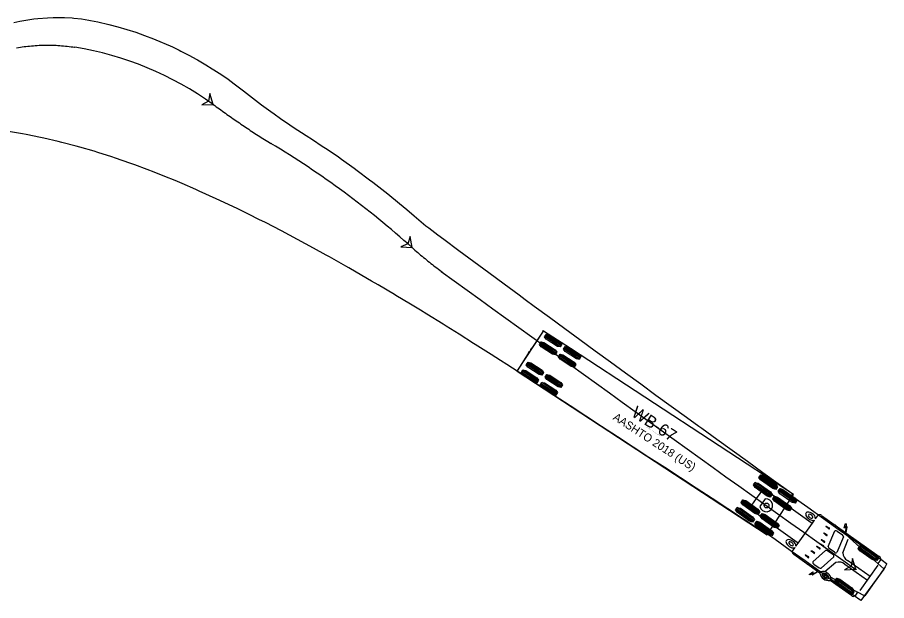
# Model space of a CAD drawing. Extents: x 973688 to 979179, y 703586 to 707602.
# Drawn here: x 977227.3 to 977381.2, y 703955.6 to 704058.8 of the extents above; entities that cross this region are included whole.
import ezdxf

# ---------------------------------------------------------------- set-up
doc = ezdxf.new("R2010")
doc.units = 0
doc.layers.add('SB Right', color=7, linetype='Continuous')

msp = doc.modelspace()

# ---------------------------------------------------------------- linework, layer by layer
at = {"layer": 'SB Right'}
for p, q in [((977315.78, 703996.2), (977320.43, 704003.32)), ((977320.34, 704003.32), (977318.35, 704000.28)), ((977320.34, 704003.32), (977320.34, 704003.32)), ((977320.37, 704003.36), (977320.35, 704003.34)), ((977320.43, 704003.32), (977320.37, 704003.36)), ((977325.17, 704000.22), (977320.43, 704003.32)), ((977323.41, 704000.55), (977320.64, 704002.36)), ((977323.53, 704000.74), (977320.77, 704002.55)), ((977323.66, 704000.94), (977320.89, 704002.74)), ((977318.18, 704000.02), (977317.9, 703999.58)), ((977318.27, 704000.28), (977318.13, 704000.06)), ((977318.19, 704000.02), (977318.33, 704000.25)), ((977318.33, 704000.25), (977318.27, 704000.28)), ((977318.27, 704000.28), (977318.27, 704000.28)), ((977318.35, 704000.28), (977318.33, 704000.25)), ((977322.5, 703999.17), (977319.74, 704000.98)), ((977322.63, 703999.36), (977319.87, 704001.17)), ((977322.75, 703999.56), (977319.99, 704001.36)), ((977326.76, 703998.37), (977323.99, 704000.17)), ((977326.88, 703998.56), (977324.12, 704000.36)), ((977327.01, 703998.75), (977324.24, 704000.55)), ((977364.68, 703974.42), (977325.17, 704000.22)), ((977317.73, 703999.33), (977315.74, 703996.28)), ((977317.84, 703999.62), (977317.69, 703999.4)), ((977317.69, 703999.4), (977317.69, 703999.39)), ((977317.69, 703999.39), (977317.75, 703999.36)), ((977317.75, 703999.36), (977317.73, 703999.33)), ((977317.75, 703999.36), (977317.9, 703999.58)), ((977318.04, 703999.8), (977318.1, 703999.76)), ((977325.85, 703996.98), (977323.09, 703998.79)), ((977325.98, 703997.18), (977323.22, 703998.98)), ((977326.1, 703997.37), (977323.34, 703999.17)), ((977320.16, 703995.59), (977317.4, 703997.39)), ((977320.29, 703995.78), (977317.52, 703997.58)), ((977320.41, 703995.97), (977317.65, 703997.77)), ((977315.73, 703996.26), (977315.72, 703996.24)), ((977315.72, 703996.24), (977315.78, 703996.2)), ((977315.74, 703996.28), (977315.74, 703996.28)), ((977315.78, 703996.2), (977320.52, 703993.11)), ((977319.26, 703994.2), (977316.5, 703996.01)), ((977319.39, 703994.4), (977316.62, 703996.2)), ((977319.51, 703994.59), (977316.75, 703996.39)), ((977323.76, 703993.78), (977321, 703995.59)), ((977322.73, 703992.21), (977319.97, 703994.01)), ((977322.86, 703992.4), (977320.1, 703994.2)), ((977323.51, 703993.4), (977320.75, 703995.2)), ((977323.64, 703993.59), (977320.87, 703995.39)), ((977322.61, 703992.02), (977319.85, 703993.82)), ((977320.52, 703993.11), (977360.03, 703967.3)), ((977361.55, 703975.35), (977358.57, 703977.48)), ((977361.69, 703975.54), (977358.7, 703977.67)), ((977361.82, 703975.72), (977358.84, 703977.85)), ((977360.6, 703974.01), (977357.61, 703976.14)), ((977360.73, 703974.19), (977357.74, 703976.32)), ((977360.86, 703974.38), (977357.88, 703976.51)), ((977358.14, 703973.72), (977359.4, 703975.48)), ((977359.4, 703975.48), (977367.83, 703969.46)), ((977365.24, 703973.28), (977362.25, 703975.41)), ((977364.15, 703971.75), (977361.16, 703973.88)), ((977364.28, 703971.94), (977361.3, 703974.07)), ((977364.97, 703972.91), (977361.99, 703975.04)), ((977365.11, 703973.1), (977362.12, 703975.23)), ((977362.36, 703970.86), (977364.68, 703974.42)), ((977358.4, 703970.93), (977355.41, 703973.06)), ((977358.53, 703971.11), (977355.55, 703973.24)), ((977358.66, 703971.3), (977355.68, 703973.43)), ((977356.88, 703971.96), (977358.14, 703973.72)), ((977359.66, 703973.62), (977358.72, 703972.31)), ((977364.01, 703971.57), (977361.03, 703973.7)), ((977357.44, 703969.58), (977354.45, 703971.72)), ((977357.57, 703969.77), (977354.59, 703971.9)), ((977357.7, 703969.96), (977354.72, 703972.09)), ((977365.31, 703965.94), (977356.88, 703971.96)), ((977361.95, 703968.67), (977358.96, 703970.8)), ((977362.08, 703968.86), (977359.1, 703970.99)), ((977360.03, 703967.3), (977362.36, 703970.86)), ((977368.58, 703970.11), (977369.08, 703970.8)), ((977360.86, 703967.14), (977357.87, 703969.27)), ((977360.99, 703967.33), (977358.01, 703969.46)), ((977361.12, 703967.52), (977358.14, 703969.65)), ((977361.82, 703968.49), (977358.83, 703970.62)), ((977365.51, 703965.8), (977368.02, 703969.32)), ((977367.83, 703969.46), (977368.02, 703969.32)), ((977368.02, 703969.32), (977368.42, 703969.88)), ((977369.65, 703970.72), (977373.86, 703967.71)), ((977373.67, 703968.54), (977373.87, 703969.28)), ((977373.87, 703969.28), (977373.88, 703969.28)), ((977373.88, 703969.28), (977373.97, 703969.21)), ((977370.41, 703968.76), (977370.47, 703968.83)), ((977370.84, 703968.41), (977370.41, 703968.76)), ((977370.47, 703968.83), (977370.94, 703968.54)), ((977370.81, 703965.19), (977371.99, 703967.96)), ((977372.03, 703969.02), (977379.61, 703962.19)), ((977372.4, 703967.91), (977373.33, 703967.25)), ((977373.75, 703968.48), (977373.67, 703968.54)), ((977373.96, 703968.76), (977373.75, 703968.48)), ((977373.86, 703967.71), (977374.05, 703968.68)), ((977373.86, 703967.71), (977373.95, 703967.66)), ((977374.14, 703968.64), (977373.95, 703967.67)), ((977373.97, 703968.76), (977373.96, 703968.76)), ((977373.97, 703969.21), (977373.97, 703969.21)), ((977373.97, 703969.21), (977373.98, 703968.81)), ((977373.97, 703968.76), (977373.98, 703968.78)), ((977374.03, 703968.71), (977373.97, 703968.76)), ((977373.98, 703968.78), (977373.98, 703968.81)), ((977373.98, 703968.81), (977373.98, 703968.81)), ((977373.98, 703968.81), (977374.05, 703968.76)), ((977374.05, 703968.68), (977374.03, 703968.71)), ((977374.03, 703968.71), (977374.03, 703968.71)), ((977374.03, 703968.71), (977374.03, 703968.71)), ((977374.05, 703968.68), (977374.05, 703968.68)), ((977369.58, 703966.36), (977369.64, 703966.43)), ((977370.01, 703966.01), (977369.58, 703966.36)), ((977369.64, 703966.43), (977370.11, 703966.14)), ((977370.02, 703967.54), (977370.07, 703967.62)), ((977370.47, 703967.18), (977370.02, 703967.54)), ((977370.07, 703967.62), (977370.56, 703967.32)), ((977373.53, 703966.9), (977372.35, 703964.13)), ((977373.43, 703964.11), (977374.35, 703966.49)), ((977373.95, 703967.67), (977373.95, 703967.65)), ((977373.95, 703967.65), (977379.86, 703963.43)), ((977364.45, 703964.32), (977364.94, 703965.01)), ((977365.11, 703965.24), (977365.51, 703965.8)), ((977365.51, 703965.8), (977365.31, 703965.94)), ((977368.76, 703965.21), (977368.82, 703965.28)), ((977369.19, 703964.86), (977368.76, 703965.21)), ((977368.82, 703965.28), (977369.29, 703964.99)), ((977369.43, 703965.6), (977369.48, 703965.68)), ((977369.85, 703965.25), (977369.43, 703965.6)), ((977369.48, 703965.68), (977369.95, 703965.39)), ((977371.93, 703964.19), (977371.01, 703964.85)), ((977379.14, 703962.8), (977376.15, 703964.93)), ((977379.27, 703962.99), (977376.28, 703965.11)), ((977379.4, 703963.18), (977376.41, 703965.3)), ((977368.92, 703960.8), (977364.71, 703963.8)), ((977366.76, 703963.65), (977366.82, 703963.72)), ((977367.19, 703963.29), (977366.76, 703963.65)), ((977366.82, 703963.72), (977367.29, 703963.43)), ((977367.78, 703964.41), (977367.84, 703964.49)), ((977368.21, 703964.06), (977367.78, 703964.41)), ((977367.84, 703964.49), (977368.31, 703964.2)), ((977370.31, 703964.5), (977368.08, 703962.49)), ((977369.59, 703961.38), (977371.82, 703963.39)), ((977371.63, 703963.77), (977370.71, 703964.42)), ((977379.12, 703962.95), (977379.36, 703963.28)), ((977379.36, 703963.28), (977379.65, 703963.08)), ((977367.09, 703962.1), (977369.55, 703960.74)), ((977368.27, 703962.11), (977369.19, 703961.46)), ((977372.19, 703962.37), (977370.23, 703960.72)), ((977377.75, 703959.2), (977373.77, 703962.04)), ((977378.24, 703959.88), (977374.26, 703962.72)), ((977376.46, 703957.4), (977379.69, 703961.92)), ((977379.41, 703962.74), (977379.12, 703962.95)), ((977379.65, 703963.08), (977379.41, 703962.74)), ((977380.11, 703962.89), (977379.61, 703962.19)), ((977379.61, 703962.19), (977379.61, 703962.19)), ((977379.61, 703962.19), (977380.67, 703961.23)), ((977367.45, 703960.28), (977368.08, 703960.71)), ((977367.54, 703960.21), (977367.45, 703960.28)), ((977367.45, 703960.28), (977367.45, 703960.28)), ((977367.55, 703960.21), (977367.54, 703960.21)), ((977367.93, 703960.33), (977367.55, 703960.21)), ((977367.95, 703960.34), (977367.93, 703960.33)), ((977368, 703960.28), (977367.93, 703960.33)), ((977367.93, 703960.33), (977367.93, 703960.33)), ((977367.97, 703960.36), (977367.95, 703960.34)), ((977368.16, 703960.65), (977367.97, 703960.36)), ((977367.97, 703960.36), (977367.97, 703960.36)), ((977367.97, 703960.36), (977368.04, 703960.31)), ((977368.04, 703960.31), (977368.04, 703960.31)), ((977368.04, 703960.31), (977368.04, 703960.31)), ((977368.04, 703960.31), (977368.07, 703960.3)), ((977368.07, 703960.3), (977368.92, 703960.8)), ((977368.07, 703960.3), (977368.07, 703960.3)), ((977368.08, 703960.71), (977368.16, 703960.65)), ((977369, 703960.73), (977368.13, 703960.24)), ((977368.92, 703960.8), (977369.01, 703960.74)), ((977369.01, 703960.73), (977369, 703960.73)), ((977369.36, 703960.49), (977369.01, 703960.73)), ((977380.64, 703961.17), (977378.97, 703958.84)), ((977380.67, 703961.23), (977380.64, 703961.17)), ((977374.92, 703956.52), (977371.14, 703959.21)), ((977371.27, 703959.79), (977376.02, 703957.16)), ((977375.02, 703957.04), (977372.03, 703959.16)), ((977375.15, 703957.22), (977372.17, 703959.35)), ((977375.29, 703957.41), (977372.3, 703959.53)), ((977378.97, 703958.84), (977377.31, 703956.51)), ((977375.14, 703957.37), (977374.9, 703957.03)), ((977374.9, 703957.03), (977375.19, 703956.83)), ((977375.43, 703957.16), (977375.14, 703957.37)), ((977375.19, 703956.83), (977375.43, 703957.16)), ((977376.01, 703957.15), (977375.51, 703956.45)), ((977376.02, 703957.16), (977376.01, 703957.15)), ((977377.27, 703956.46), (977376.02, 703957.16)), ((977377.31, 703956.51), (977377.27, 703956.46))]:
    msp.add_line(p, q, dxfattribs=at)
for points in [[(977226.66, 704057.93), (977227.72, 704058.15), (977229.48, 704058.45), (977230.18, 704058.55), (977230.87, 704058.63), (977232.59, 704058.76), (977233.61, 704058.8), (977234.28, 704058.81), (977235.63, 704058.79), (977236.96, 704058.71), (977237.29, 704058.68), (977238.61, 704058.54), (977239.91, 704058.34), (977240.23, 704058.28), (977241.52, 704058.01), (977243.44, 704057.57), (977245.04, 704057.14), (977246.64, 704056.68), (977248.22, 704056.17), (977249.79, 704055.62), (977251.35, 704055.03), (977252.89, 704054.4), (977253.2, 704054.26), (977254.73, 704053.58), (977255.93, 704053), (977256.23, 704052.86), (977257.72, 704052.09), (977258.9, 704051.45), (977259.19, 704051.29), (977260.64, 704050.44), (977261.78, 704049.74), (977262.07, 704049.56), (977263.47, 704048.63), (977264.58, 704047.86), (977265.68, 704047.07), (977267.3, 704045.84), (977269.98, 704043.77), (977270.52, 704043.36), (977272.16, 704042.14), (977272.72, 704041.74), (977273.83, 704040.94), (977275.52, 704039.78), (977276.09, 704039.41), (977278.39, 704037.94), (977279.54, 704037.19), (977281.26, 704036.06), (977282.12, 704035.49), (977284.1, 704034.13), (977284.66, 704033.74), (977286.89, 704032.14), (977287.45, 704031.74), (977289.64, 704030.1), (977290.18, 704029.69), (977292.32, 704028.02), (977292.85, 704027.6), (977294.95, 704025.9), (977296.25, 704024.82), (977297.53, 704023.73), (977299.56, 704021.96), (977300.09, 704021.56), (977301.7, 704020.36), (977302.77, 704019.57), (977305.43, 704017.6), (977308.09, 704015.63), (977310.75, 704013.66), (977313.43, 704011.69), (977316.11, 704009.71), (977317.18, 704008.92), (977318.79, 704007.73), (977321.48, 704005.76), (977324.17, 704003.79), (977326.86, 704001.82), (977329.55, 703999.85), (977332.25, 703997.88), (977334.94, 703995.92), (977337.63, 703993.96), (977340.33, 703992), (977343.03, 703990.04), (977345.73, 703988.08), (977347.89, 703986.52), (977348.43, 703986.13), (977351.13, 703984.18), (977353.83, 703982.23), (977356.53, 703980.28), (977359.24, 703978.33), (977361.94, 703976.38), (977364.39, 703974.63), (977364.45, 703974.12), (977367.2, 703972.16), (977369.98, 703970.18), (977372.78, 703968.18), (977375.57, 703966.19), (977377.58, 703964.75), (977378.52, 703964.08), (977379.45, 703963.42), (977380.35, 703962.78), (977381.12, 703962.22), (977381.16, 703962.11), (977380.88, 703961.64), (977380.02, 703960.33), (977376.58, 703955.64), (977376.33, 703955.81), (977376.25, 703955.87), (977375.58, 703956.35), (977374.67, 703956.99), (977373.77, 703957.63), (977372.89, 703958.26), (977372.01, 703958.88), (977369.35, 703960.78), (977366.71, 703962.65), (977364.07, 703964.53), (977361.41, 703966.43), (977360.07, 703967.38), (977359.74, 703967.49), (977358.63, 703968.21), (977355.85, 703970.03), (977353.05, 703971.86), (977350.26, 703973.68), (977347.47, 703975.51), (977344.67, 703977.33), (977341.88, 703979.16), (977339.08, 703980.98), (977336.29, 703982.81), (977333.5, 703984.63), (977330.71, 703986.45), (977327.91, 703988.28), (977325.12, 703990.1), (977322.33, 703991.93), (977319.54, 703993.75), (977318.7, 703994.3), (977316.74, 703995.57), (977313.94, 703997.38), (977312.82, 703998.1), (977311.14, 703999.18), (977308.32, 704000.97), (977308.04, 704001.15), (977305.49, 704002.75), (977303.21, 704004.18), (977302.64, 704004.53), (977299.77, 704006.3), (977298.62, 704007.01), (977296.89, 704008.06), (977294.3, 704009.62), (977294.01, 704009.79), (977291.13, 704011.5), (977289.99, 704012.17), (977288.27, 704013.17), (977285.97, 704014.49), (977285.4, 704014.82), (977282.54, 704016.43), (977281.97, 704016.75), (977279.69, 704018), (977278.28, 704018.78), (977276.86, 704019.54), (977274.03, 704021.04), (977271.18, 704022.5), (977270.04, 704023.08), (977268.31, 704023.94), (977266.28, 704024.93), (977265.41, 704025.35), (977262.48, 704026.73), (977259.47, 704028.09), (977258.86, 704028.36), (977256.43, 704029.41), (977255.21, 704029.93), (977253.36, 704030.68), (977251.51, 704031.41), (977250.27, 704031.89), (977248.09, 704032.7), (977247.16, 704033.04), (977244.65, 704033.91), (977244.02, 704034.12), (977241.49, 704034.92), (977240.86, 704035.12), (977238.32, 704035.86), (977237.68, 704036.03), (977235.14, 704036.7), (977234.51, 704036.86), (977231.97, 704037.44), (977231.34, 704037.58), (977228.82, 704038.09), (977228.19, 704038.21), (977225.71, 704038.64)], [(977227.14, 704053.44), (977227.47, 704053.5), (977227.8, 704053.55), (977228.13, 704053.59), (977228.46, 704053.64), (977228.79, 704053.68), (977229.12, 704053.71), (977229.45, 704053.75), (977229.79, 704053.78), (977230.12, 704053.81), (977230.45, 704053.83), (977230.78, 704053.85), (977231.12, 704053.87), (977231.45, 704053.88), (977231.78, 704053.9), (977232.12, 704053.9), (977232.45, 704053.91), (977232.78, 704053.91), (977233.12, 704053.91), (977233.45, 704053.9), (977233.78, 704053.89), (977234.12, 704053.88), (977234.45, 704053.86), (977234.78, 704053.84), (977235.11, 704053.81), (977235.45, 704053.78), (977235.78, 704053.75), (977236.11, 704053.72), (977236.44, 704053.68), (977236.77, 704053.63), (977237.1, 704053.58), (977237.43, 704053.53)], [(977261.94, 704043.4), (977261.36, 704045.32), (977261.13, 704043.98), (977259.94, 704043.33), (977261.94, 704043.4)], [(977261.94, 704043.4), (977262.21, 704043.21), (977262.48, 704043.01), (977262.75, 704042.82), (977263.03, 704042.62), (977263.3, 704042.43), (977263.57, 704042.24), (977263.84, 704042.04), (977264.11, 704041.85), (977264.38, 704041.66), (977264.65, 704041.46), (977264.93, 704041.27), (977265.2, 704041.08), (977265.47, 704040.89), (977265.75, 704040.7), (977266.02, 704040.51), (977266.29, 704040.32), (977266.57, 704040.13), (977266.84, 704039.94), (977267.12, 704039.75), (977267.4, 704039.57), (977267.67, 704039.38), (977267.95, 704039.19), (977268.23, 704039.01), (977268.5, 704038.82), (977268.78, 704038.64), (977269.06, 704038.46), (977269.34, 704038.28), (977269.62, 704038.1), (977269.9, 704037.92), (977270.18, 704037.74), (977270.46, 704037.56), (977270.75, 704037.38), (977271.03, 704037.21), (977271.31, 704037.03), (977271.6, 704036.86), (977271.88, 704036.69), (977272.17, 704036.51)], [(977297.16, 704018.09), (977296.79, 704020.05), (977296.42, 704018.75), (977295.17, 704018.24), (977297.16, 704018.09)], [(977297.16, 704018.09), (977297.41, 704017.87), (977297.66, 704017.64), (977297.91, 704017.42), (977298.16, 704017.21), (977298.42, 704016.99), (977298.67, 704016.77), (977298.92, 704016.56), (977299.18, 704016.34), (977299.44, 704016.13), (977299.69, 704015.92), (977299.95, 704015.71), (977300.21, 704015.5), (977300.47, 704015.29), (977300.74, 704015.08), (977301, 704014.88), (977301.26, 704014.68), (977301.53, 704014.48), (977301.8, 704014.28), (977302.06, 704014.08), (977302.33, 704013.88)], [(977375.72, 703961.17), (977375.13, 703963.08), (977374.9, 703961.75), (977373.72, 703961.09), (977375.72, 703961.17)]]:
    msp.add_lwpolyline(points, dxfattribs=at)
for points in [[(977261.94, 704043.4), (977261.36, 704045.32), (977261.13, 704043.98), (977259.94, 704043.33)], [(977297.16, 704018.09), (977296.79, 704020.05), (977296.42, 704018.75), (977295.17, 704018.24)], [(977323.69, 704000.98), (977323.38, 704000.51), (977322.89, 704000.61), (977320.9, 704001.91), (977320.61, 704002.31), (977320.93, 704002.79), (977321.41, 704002.68), (977323.4, 704001.38)], [(977322.79, 703999.6), (977322.47, 703999.12), (977321.99, 703999.23), (977320, 704000.53), (977319.71, 704000.93), (977320.02, 704001.41), (977320.5, 704001.3), (977322.49, 704000)], [(977327.04, 703998.8), (977326.72, 703998.32), (977326.24, 703998.43), (977324.25, 703999.73), (977323.96, 704000.12), (977324.27, 704000.6), (977324.76, 704000.49), (977326.74, 703999.19)], [(977326.13, 703997.42), (977325.82, 703996.94), (977325.34, 703997.05), (977323.35, 703998.34), (977323.06, 703998.74), (977323.37, 703999.22), (977323.85, 703999.11), (977325.84, 703997.81)], [(977320.44, 703996.02), (977320.13, 703995.54), (977319.65, 703995.65), (977317.66, 703996.95), (977317.37, 703997.34), (977317.68, 703997.82), (977318.16, 703997.71), (977320.15, 703996.41)], [(977319.54, 703994.64), (977319.23, 703994.16), (977318.75, 703994.26), (977316.76, 703995.56), (977316.47, 703995.96), (977316.78, 703996.44), (977317.26, 703996.33), (977319.25, 703995.03)], [(977323.79, 703993.83), (977323.48, 703993.35), (977323, 703993.46), (977321.01, 703994.76), (977320.72, 703995.16), (977321.03, 703995.63), (977321.51, 703995.53), (977323.5, 703994.23)], [(977322.89, 703992.45), (977322.58, 703991.97), (977322.1, 703992.08), (977320.11, 703993.38), (977319.81, 703993.77), (977320.13, 703994.25), (977320.61, 703994.14), (977322.6, 703992.84)], [(977361.85, 703975.77), (977361.52, 703975.3), (977361, 703975.46), (977358.85, 703977), (977358.54, 703977.43), (977358.87, 703977.9), (977359.39, 703977.74), (977361.54, 703976.21)], [(977360.89, 703974.43), (977360.56, 703973.96), (977360.04, 703974.12), (977357.9, 703975.65), (977357.58, 703976.09), (977357.91, 703976.56), (977358.43, 703976.4), (977360.58, 703974.86)], [(977365.27, 703973.33), (977364.94, 703972.86), (977364.42, 703973.02), (977362.27, 703974.55), (977361.96, 703974.99), (977362.29, 703975.46), (977362.81, 703975.3), (977364.95, 703973.77)], [(977364.31, 703971.99), (977363.98, 703971.52), (977363.46, 703971.68), (977361.31, 703973.21), (977361, 703973.65), (977361.33, 703974.12), (977361.85, 703973.96), (977364, 703972.42)], [(977358.7, 703971.35), (977358.36, 703970.88), (977357.85, 703971.04), (977355.7, 703972.57), (977355.38, 703973.01), (977355.71, 703973.48), (977356.23, 703973.32), (977358.38, 703971.79)], [(977357.74, 703970), (977357.41, 703969.54), (977356.89, 703969.7), (977354.74, 703971.23), (977354.42, 703971.67), (977354.75, 703972.13), (977355.27, 703971.98), (977357.42, 703970.44)], [(977362.11, 703968.91), (977361.78, 703968.44), (977361.26, 703968.6), (977359.12, 703970.13), (977358.8, 703970.57), (977359.13, 703971.04), (977359.65, 703970.88), (977361.8, 703969.35)], [(977361.16, 703967.56), (977360.82, 703967.1), (977360.31, 703967.26), (977358.16, 703968.79), (977357.84, 703969.23), (977358.17, 703969.69), (977358.69, 703969.54), (977360.84, 703968)], [(977379.43, 703963.22), (977379.1, 703962.76), (977378.58, 703962.91), (977376.43, 703964.44), (977376.11, 703964.88), (977376.45, 703965.35), (977376.96, 703965.19), (977379.12, 703963.66)], [(977375.72, 703961.17), (977375.13, 703963.08), (977374.9, 703961.75), (977373.72, 703961.09)], [(977375.32, 703957.46), (977374.99, 703956.99), (977374.47, 703957.15), (977372.32, 703958.68), (977372, 703959.11), (977372.33, 703959.58), (977372.85, 703959.42), (977375, 703957.89)]]:
    msp.add_lwpolyline(points, close=True, dxfattribs=at)
for centre, radius in [((977237.43, 704053.53), 0.0417), ((977237.43, 704053.53), 0.0417), ((977261.94, 704043.4), 0.0417), ((977261.94, 704043.4), 0.0417), ((977272.17, 704036.51), 0.0417), ((977272.17, 704036.51), 0.0417), ((977297.16, 704018.09), 0.0417), ((977297.16, 704018.09), 0.0417), ((977302.33, 704013.88), 0.0417), ((977302.33, 704013.88), 0.0417), ((977320.32, 704003.35), 0.0266), ((977315.71, 703996.29), 0.0266), ((977359.91, 703972.46), 0.424), ((977375.72, 703961.17), 0.0417)]:
    msp.add_circle(centre, radius, dxfattribs=at)
for centre, radius, start, end in [((977228.21, 703996.5), 57.78, 54.2771, 80.8173), ((977187.58, 703895.6), 164.35, 48.1817, 59.0237), ((982472.11, 711133.52), 8798.63, 234.015474, 234.603854), ((977320.32, 704003.35), 0.0363, 345.9285, 307.0898), ((977318.16, 704000.04), 0.0352, 146.8763, 325.8767), ((977318.16, 704000.04), 0.0353, 330.1872, 148.5369), ((977317.87, 703999.6), 0.0354, 151.1426, 323.3281), ((977317.87, 703999.6), 0.0352, 327.8254, 146.8258), ((977314.04, 703997.37), 2.02, 326.8511, 327.5348), ((977359.84, 703972.49), 1.14, 189.4759, 99.4759), ((977367.17, 703970.95), 0.346, 87.8686, 184.8816), ((977367.95, 703971.12), 1.14, 190.2398, 231.7606), ((977367.17, 703969.88), 1.42, 52.404, 89.4719), ((977367.47, 703970.73), 0.172, 84.7775, 171.9281), ((977367.46, 703970.24), 0.664, 49.3797, 87.6014), ((977367.45, 703970.03), 1.14, 4.1058, 58.8971), ((977369.29, 703970.22), 0.619, 54.4739, 110.3156), ((977368.4, 703971.52), 1.73, 228.3025, 253.101), ((977367.66, 703970.75), 0.362, 178.7724, 227.8134), ((977367.98, 703970.95), 0.732, 219.6497, 265.8841), ((977367.6, 703970.31), 0.522, 9.4812, 56.6454), ((977368.14, 703970.55), 0.729, 250.2844, 292.7984), ((977367.95, 703970.39), 0.169, 262.9102, 3.0289), ((977370.98, 703968.53), 0.184, 221.4291, 293.3211), ((977370.9, 703968.39), 0.157, 348.0219, 75.1315), ((977372.16, 703967.68), 0.332, 43.3973, 121.8193), ((977374.06, 703968.65), 0.108, 45.317, 91.4995), ((977374.1, 703968.68), 0.0522, 310.7387, 55.5933), ((977363.69, 703966.07), 0.346, 104.0701, 201.0832), ((977363.78, 703965.28), 1.14, 57.1912, 98.7119), ((977363.55, 703964.73), 1.73, 35.8507, 60.6492), ((977370.58, 703967.31), 0.184, 221.4291, 293.3211), ((977370.5, 703967.18), 0.157, 348.0219, 75.1315), ((977373.14, 703966.91), 0.387, 358.8087, 62.0407), ((977364.7, 703966.42), 1.42, 199.4799, 236.5477), ((977363.99, 703965.86), 0.172, 117.0237, 204.1743), ((977364.45, 703966.03), 0.664, 201.3503, 239.572), ((977364.04, 703965.67), 0.362, 61.1383, 110.1793), ((977364.65, 703966.11), 1.14, 230.0546, 284.8459), ((977364.44, 703965.87), 0.522, 232.3064, 279.4705), ((977363.96, 703965.31), 0.732, 23.0676, 69.3021), ((977364.48, 703965.52), 0.169, 285.9228, 26.0416), ((977364.38, 703965.29), 0.729, 356.1534, 38.6674), ((977369.32, 703964.95), 0.157, 213.8202, 300.9299), ((977369.22, 703964.82), 0.184, 355.6307, 67.5227), ((977369.98, 703965.34), 0.157, 213.8202, 300.9299), ((977369.91, 703965.24), 0.157, 348.0219, 75.1315), ((977370.15, 703966.13), 0.184, 221.4291, 293.3211), ((977370.07, 703965.99), 0.157, 348.0219, 75.1315), ((977371.19, 703965.19), 0.387, 178.8112, 242.0382), ((977365.07, 703964.31), 0.619, 178.6362, 234.4779), ((977367.32, 703963.38), 0.157, 213.8202, 300.9299), ((977367.21, 703963.26), 0.184, 355.6307, 67.5227), ((977368.34, 703964.15), 0.157, 213.8202, 300.9299), ((977368.24, 703964.03), 0.184, 355.6307, 67.5227), ((977370.45, 703964.14), 0.387, 46.9135, 110.1406), ((977371.54, 703963.49), 0.296, 341.1946, 71.4923), ((977372.17, 703964.37), 0.296, 217.4594, 307.7571), ((977374.95, 703964.07), 1.52, 178.4684, 242.8958), ((977379.64, 703963), 0.486, 346.9388, 62.8899), ((977368.41, 703962.42), 0.332, 167.1325, 245.5545), ((977372.72, 703960.95), 1.52, 46.0559, 110.4833), ((977368.1, 703960.31), 0.108, 197.4522, 243.6347), ((977368.09, 703960.26), 0.0522, 233.3585, 338.2131), ((977369.45, 703961.74), 0.387, 226.9111, 290.143), ((977369.7, 703960.43), 0.347, 116.8031, 171.6137), ((977370.87, 703960.72), 1.53, 188.9686, 279.9777), ((977369.88, 703959.66), 1.14, 53.1804, 106.983), ((977370.05, 703960.22), 0.317, 150.3261, 211.9185), ((977370.06, 703960.04), 0.44, 66.2701, 130.083), ((977370.7, 703960.53), 1.03, 207.2995, 235.686), ((977370.2, 703960.11), 0.17, 152.1449, 206.2093), ((977370.21, 703959.98), 0.263, 53.4108, 127.3127), ((977370.57, 703960.3), 0.589, 207.2314, 250.2141), ((977369.86, 703959.32), 1.19, 35.6071, 71.4964), ((977370.11, 703959.67), 0.575, 27.551, 64.1213), ((977369.72, 703959.09), 1.7, 24.3966, 60.3046), ((977370.57, 703959.75), 0.366, 332.5282, 45.0092), ((977370.57, 703960.13), 0.634, 225.0597, 301.0615), ((977370.48, 703959.94), 0.223, 241.7108, 311.3133), ((977370.49, 703959.86), 0.158, 329.4471, 30.9598), ((977370.9, 703959.58), 0.425, 302.5388, 29.0752), ((977375.26, 703956.87), 0.486, 226.0618, 302.0129)]:
    msp.add_arc(centre, radius, start, end, dxfattribs=at)
for centre, major_axis, start_param, end_param in [((977374.1, 703968.7), (0.0637, -0.0455), 2.615166, 3.884468), ((977374.1, 703968.7), (-0.0637, 0.0455), 1.301202, 2.571945), ((977368.07, 703960.26), (0.0637, -0.0455), 2.398717, 3.668019), ((977368.07, 703960.26), (0.0637, -0.0455), 0.569648, 1.840391)]:
    msp.add_ellipse(centre, major_axis=major_axis, ratio=0.544872, start_param=start_param, end_param=end_param, dxfattribs=at)

# ---------------------------------------------------------------- texts
for s, height, p in [('WB-67', 2.125, (977335.82, 703988.4)), ('AASHTO 2018 (US)', 1.4167, (977332.59, 703987.76)), ('(c) 2022 Transoft Solutions, Inc. All rights reserved.', 0.085, (977338.69, 703986.27))]:
    msp.add_text(s, height=height, rotation=326.8511, dxfattribs=at).set_placement(p)

doc.saveas('drawing.dxf')
